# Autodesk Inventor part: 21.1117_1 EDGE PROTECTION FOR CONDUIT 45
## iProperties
Created: 2007-05
Part Number: 21.1117_1 EDGE PROTECTION FOR CONDUIT 45
Document SubType Name: Modeling
Designer: Andy Moles
Material: ABS Plastic
Density: 1.06 g/cm^3
Author: Andy Moles
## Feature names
1. Extrusion1
2. Fillet1
3. Extrusion3
4. Extrusion4
5. Fillet2
